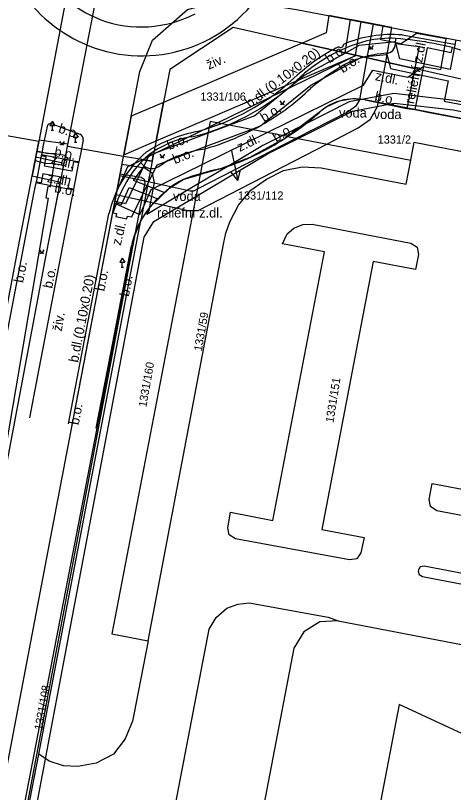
# Model space of a CAD drawing. Extents: x -601602 to -600882, y -1162594 to -1161950.
# Drawn here: x -601319.6 to -601273.9, y -1162415.3 to -1162334.3 of the extents above; entities that cross this region are included whole.
import ezdxf

# ---------------------------------------------------------------- set-up
doc = ezdxf.new("R2010")
doc.units = 0
for name, color, linetype in [('KN_Hranice parcel', 7, 'Continuous'), ('KN_Parcelní čísla', 7, 'Continuous'), ('KN_Pop  PČ popisy', 7, 'Continuous'), ('KN_Věcná břemena k části', 7, 'Continuous'), ('Vrstva 13', 7, 'Continuous'), ('Vrstva 16', 7, 'Continuous'), ('VRSTVA 3', 7, 'Continuous'), ('Vrstva 8', 7, 'Continuous')]:
    doc.layers.add(name, color=color, linetype=linetype)

# ---------------------------------------------------------------- blocks, each defined once
blk = doc.blocks.new('1029_20')
at = {"layer": 'KN_Pop  PČ popisy'}
for p, q in [((0, 0), (0.624, -2.935)), ((0.624, -2.935), (-0.074, -2.06)), ((0.624, -2.935), (0.906, -1.852))]:
    blk.add_line(p, q, dxfattribs=at)

msp = doc.modelspace()

# ---------------------------------------------------------------- linework, layer by layer
at = {"layer": 'KN_Hranice parcel'}
for p, q in [((-601314.03, -1162331.01), (-601317.17, -1162347.42)), ((-601314.18, -1162347.94), (-601311.29, -1162333.02)), ((-601317.17, -1162347.42), (-601323.06, -1162346.39)), ((-601291.23, -1162346.89), (-601278.38, -1162349.37)), ((-601308.33, -1162348.97), (-601314.18, -1162347.94)), ((-601305.34, -1162349.49), (-601308.33, -1162348.97)), ((-601305.34, -1162349.49), (-601306.52, -1162355.67)), ((-601317.16, -1162411.33), (-601306.52, -1162355.67)), ((-601318.63, -1162419.05), (-601317.16, -1162411.33))]:
    msp.add_line(p, q, dxfattribs=at)
for points in [[(-601308.33, -1162348.97), (-601306.64, -1162340.12), (-601305.31, -1162336.84), (-601301.64, -1162333.66), (-601297.4, -1162332.52), (-601290.3, -1162333.64), (-601266.25, -1162338.24), (-601260.29, -1162339.36), (-601231.3, -1162344.87), (-601139.53, -1162362.21), (-601062.38, -1162376.91), (-600987.54, -1162391.11), (-600950.39, -1162398.12), (-600929.75, -1162402.03), (-600920.358, -1162403.852)], [(-601139.85, -1162370.35), (-601175.08, -1162363.05), (-601223.43, -1162352.19), (-601296.88, -1162335.54), (-601303.51, -1162339.9), (-601305.34, -1162349.49)], [(-601139.85, -1162370.35), (-601160.69, -1162366.38), (-601240.23, -1162351.14), (-601240.29, -1162351.38), (-601283.17, -1162343.09), (-601284.42, -1162342.98), (-601285.85, -1162343.22), (-601287.2, -1162343.85), (-601291.23, -1162346.89)], [(-601291.23, -1162346.89), (-601299.28, -1162345.34), (-601300.34, -1162350.88)], [(-601291.23, -1162346.89), (-601291.42, -1162347.04), (-601295.15, -1162349.09), (-601298.21, -1162350.27), (-601300.34, -1162350.88)], [(-601342.45, -1162480.03), (-601331.27, -1162421.43), (-601325.33, -1162390.2), (-601319.3, -1162358.55), (-601317.17, -1162347.42)], [(-601341.27, -1162489.73), (-601339.53, -1162480.59), (-601328.28, -1162421.68), (-601322.37, -1162390.85), (-601316.38, -1162359.28), (-601314.18, -1162347.94)], [(-601278.38, -1162349.37), (-601278.02, -1162347.49), (-601254.54, -1162352.03), (-601255.6, -1162357.43), (-601255.57, -1162357.92), (-601255.42, -1162358.37), (-601255.14, -1162358.81), (-601254.79, -1162359.14), (-601254.3, -1162359.39), (-601253.78, -1162359.52), (-601248.91, -1162360.41), (-601255.63, -1162395.83), (-601276.99, -1162391.71), (-601277.39, -1162391.81), (-601277.58, -1162392.1), (-601277.61, -1162392.26), (-601277.52, -1162392.61), (-601277.17, -1162392.82), (-601255.44, -1162396.98)], [(-601331.86, -1162472.11), (-601325.48, -1162438.88), (-601316.05, -1162389.38), (-601308.33, -1162348.97)], [(-601305.77, -1162399.5), (-601297.86, -1162357.97), (-601297.67, -1162356.99), (-601297.26, -1162355.81), (-601296.33, -1162354.05), (-601295.05, -1162352.51), (-601293.43, -1162351.34), (-601291.64, -1162350.46), (-601289.7, -1162350.08), (-601287.72, -1162350.18), (-601278.86, -1162351.88), (-601278.38, -1162349.37)], [(-601300.34, -1162350.88), (-601309.53, -1162398.78), (-601305.77, -1162399.5)], [(-601306.52, -1162355.67), (-601305.51, -1162354.19), (-601303.5, -1162352.26), (-601302.11, -1162351.38), (-601300.34, -1162350.88)], [(-601234.25, -1162354.54), (-601234.7, -1162355.78), (-601234.11, -1162356.97), (-601234.63, -1162359.74), (-601243.89, -1162408.17), (-601267.03, -1162403.71), (-601268.2, -1162403.5), (-601269.36, -1162403.53), (-601270.46, -1162404), (-601271.29, -1162404.85), (-601271.72, -1162405.96), (-601271.71, -1162407.14), (-601271.24, -1162408.21), (-601270.39, -1162409.04), (-601269.24, -1162409.5), (-601268.45, -1162409.65), (-601268.79, -1162411.17), (-601279.61, -1162406.15), (-601285.53, -1162437.17)], [(-601306.52, -1162355.67), (-601307.3, -1162357.51), (-601317.48, -1162410.31), (-601328.81, -1162468.87), (-601328.82, -1162471.63), (-601328.74, -1162471.98)], [(-601284.77, -1162391.08), (-601296.65, -1162388.87), (-601297.3, -1162388.46), (-601297.46, -1162387.72), (-601297.16, -1162386.1), (-601292.76, -1162386.95), (-601287.37, -1162358.94), (-601291.77, -1162358.11), (-601291.26, -1162357.07), (-601290.56, -1162356.45), (-601289.65, -1162356.07), (-601288.66, -1162356.05), (-601278.36, -1162358.03), (-601277.72, -1162358.45), (-601277.59, -1162359.21), (-601277.88, -1162360.77), (-601282.29, -1162359.93), (-601287.64, -1162387.9), (-601283.24, -1162388.75), (-601283.59, -1162390.34), (-601284, -1162390.97), (-601284.77, -1162391.08)], [(-601271.75, -1162383.95), (-601267.66, -1162362.74), (-601272.09, -1162361.89), (-601271.78, -1162360.33), (-601271.37, -1162359.69), (-601270.63, -1162359.51), (-601261.34, -1162361.33), (-601260.68, -1162361.76), (-601260.53, -1162362.5), (-601260.81, -1162364.07), (-601265.22, -1162363.22), (-601269.27, -1162384.43), (-601264.86, -1162385.28), (-601265.18, -1162386.93), (-601265.59, -1162387.56), (-601266.34, -1162387.73), (-601275.68, -1162385.94), (-601276.32, -1162385.51), (-601276.46, -1162384.76), (-601276.15, -1162383.11), (-601271.75, -1162383.95)], [(-601301.62, -1162482.78), (-601280.33, -1162486.8), (-601279.35, -1162481.79), (-601277.9, -1162482.08), (-601277.64, -1162482.08), (-601277.55, -1162481.88), (-601277.52, -1162481.7), (-601272.48, -1162482.63), (-601265.97, -1162448.61), (-601302.27, -1162441.78), (-601304.31, -1162441.04), (-601306.1, -1162439.45), (-601306.76, -1162438.09), (-601306.72, -1162436.52), (-601299.4, -1162398.31), (-601298.68, -1162397.07), (-601297.55, -1162396.12), (-601296.41, -1162395.68), (-601295.22, -1162395.55), (-601286.98, -1162397.06), (-601285.95, -1162397.42)], [(-601285.95, -1162397.42), (-601287.86, -1162397.52), (-601289.54, -1162398.56), (-601290.58, -1162400.27), (-601297.91, -1162438.61), (-601297.76, -1162440.13), (-601297.11, -1162441.39), (-601296.13, -1162442.29), (-601294.57, -1162442.91), (-601265.31, -1162448.49), (-601274.56, -1162496.89), (-601274.6, -1162498.05), (-601274.28, -1162499.02), (-601273.37, -1162500.08), (-601272.15, -1162500.6), (-601303.87, -1162494.56)], [(-601285.95, -1162397.42), (-601256.61, -1162403.05), (-601255.44, -1162396.98)], [(-601305.77, -1162399.5), (-601307.27, -1162407.39), (-601307.38, -1162407.88), (-601308.15, -1162409.74), (-601309.38, -1162411.32), (-601311.16, -1162412.28), (-601313.09, -1162412.62), (-601314.58, -1162412.56), (-601316.09, -1162412.07), (-601317.16, -1162411.33)]]:
    msp.add_lwpolyline(points, dxfattribs=at)
at = {"layer": 'KN_Pop  PČ popisy'}
msp.add_line((-601297.08, -1162348.34), (-601297.03, -1162348.57), dxfattribs=at)
at = {"layer": 'KN_Věcná břemena k části'}
for points in [[(-601284.16, -1162338.42), (-601283.57, -1162334.93), (-601286.91, -1162334.29), (-601287.21, -1162336.1), (-601289.71, -1162337.17)], [(-601281, -1162339.14), (-601280.35, -1162335.54), (-601282.31, -1162335.17), (-601282.95, -1162338.7), (-601283.74, -1162343.07), (-601284.11, -1162343.72), (-601284.92, -1162344.31), (-601290.29, -1162347.08), (-601300.64, -1162352.41), (-601301.03, -1162352.61), (-601301.37, -1162352.61), (-601305.75, -1162351.64), (-601308.72, -1162350.99), (-601309.09, -1162352.95), (-601306.13, -1162353.61), (-601301.59, -1162354.61), (-601301.06, -1162354.61), (-601300.55, -1162354.61), (-601287.13, -1162347.69), (-601283.88, -1162346.01), (-601282.59, -1162345.08), (-601281.84, -1162343.77)], [(-601277.06, -1162339.6), (-601275.24, -1162339.92), (-601274.68, -1162336.7), (-601277.8, -1162336.16), (-601279.4, -1162337.25), (-601281.5, -1162336.82), (-601281.26, -1162335.37), (-601284.7, -1162334.71), (-601285.27, -1162338.17), (-601284.16, -1162338.42), (-601277.54, -1162339.92)], [(-601284.17, -1162338.5), (-601284.16, -1162338.42), (-601289.71, -1162337.17), (-601304.17, -1162343.34), (-601304.93, -1162347.36)], [(-601299.39, -1162345.93), (-601305.2, -1162348.76), (-601305.34, -1162349.49), (-601306.34, -1162349.32), (-601307.9, -1162350.08), (-601309.03, -1162352.62), (-601309.27, -1162353.87), (-601306.61, -1162355.05), (-601306.25, -1162354.24), (-601305.44, -1162352.44), (-601300.14, -1162349.83), (-601293.35, -1162346.48), (-601283.3, -1162341.53), (-601282.34, -1162339.97), (-601278.7, -1162340.71), (-601277.54, -1162339.92), (-601284.16, -1162338.42), (-601284.17, -1162338.5), (-601285.43, -1162339.11), (-601298.5, -1162345.49)], [(-601307.53, -1162344.77), (-601308.3, -1162348.8), (-601304.93, -1162347.36), (-601304.17, -1162343.34)], [(-601314.56, -1162349.88), (-601314.37, -1162348.9), (-601315.51, -1162348.72), (-601316.36, -1162348.68), (-601317.36, -1162348.44), (-601317.55, -1162349.42), (-601316.5, -1162349.68), (-601315.61, -1162349.72)], [(-601306.34, -1162349.32), (-601305.34, -1162349.49), (-601305.2, -1162348.76)], [(-601314.9, -1162351.66), (-601314.52, -1162349.7), (-601317.48, -1162349.05), (-601317.86, -1162351.01)]]:
    msp.add_lwpolyline(points, close=True, dxfattribs=at)
for points in [[(-601273.67, -1162336.82), (-601274.26, -1162339.91), (-601279.51, -1162338.79), (-601279.97, -1162337.03), (-601283.8, -1162337.42), (-601285.2, -1162338.19), (-601289.49, -1162340.55), (-601294.65, -1162344.73), (-601297.29, -1162345.72), (-601299.51, -1162346.56), (-601305.19, -1162348.71), (-601305.68, -1162348.89), (-601305.92, -1162349.39), (-601308.13, -1162353.91), (-601308.22, -1162353.89), (-601309.23, -1162353.67), (-601309.45, -1162354.86), (-601309.06, -1162354.94), (-601309.13, -1162355.24), (-601307.97, -1162355.5), (-601307.9, -1162355.2), (-601307.47, -1162355.29), (-601305.79, -1162351.84), (-601304.82, -1162349.85), (-601299.78, -1162347.95), (-601295.03, -1162346.16), (-601294.05, -1162345.79), (-601288.81, -1162341.55), (-601283.45, -1162338.58), (-601280.87, -1162338.33), (-601280.64, -1162339.22), (-601280.49, -1162339.81), (-601274.48, -1162341.09), (-601274.89, -1162343.21), (-601244.97, -1162348.96)], [(-601218.98, -1162353.53), (-601238.41, -1162350.37), (-601243.06, -1162349.26), (-601273.81, -1162343.13), (-601280.15, -1162342.41), (-601284.8, -1162343.3), (-601291.73, -1162346.8), (-601293.8, -1162347.85), (-601297.27, -1162349.91), (-601300.53, -1162351.84), (-601305.9, -1162355.03), (-601305.64, -1162354.61), (-601305.08, -1162351.7), (-601305.31, -1162350.75), (-601305.55, -1162350.59), (-601306.12, -1162350.2), (-601308.49, -1162349.83), (-601308.68, -1162350.81), (-601306.5, -1162351.16), (-601306.19, -1162351.36), (-601306.11, -1162351.72), (-601307.13, -1162357.13), (-601328.23, -1162468.65)], [(-601326.07, -1162462.59), (-601306.17, -1162357.4), (-601305.17, -1162355.77), (-601300.78, -1162353.16), (-601293.32, -1162348.72), (-601290.12, -1162347.11), (-601284.47, -1162344.26), (-601280.11, -1162343.42), (-601273.96, -1162344.12), (-601243.27, -1162350.24), (-601238.6, -1162351.35), (-601219.15, -1162354.51), (-601164.77, -1162365.18), (-601141.49, -1162369.75)], [(-601322.37, -1162390.85), (-601316.38, -1162359.28), (-601315.17, -1162353.02), (-601314.18, -1162347.94), (-601314.13, -1162347.7), (-601317.15, -1162347.29), (-601317.17, -1162347.42), (-601317.37, -1162348.47), (-601315.42, -1162348.73), (-601315.97, -1162352.15), (-601316.22, -1162352.11), (-601316.42, -1162353.31), (-601316.17, -1162353.35), (-601322.79, -1162391.91)]]:
    msp.add_lwpolyline(points, dxfattribs=at)
at = {"layer": 'Vrstva 13'}
for p, q in [((-601279.98, -1162337.2), (-601279.95, -1162336.66)), ((-601279.28, -1162336.31), (-601273.82, -1162337.26)), ((-601279.98, -1162337.2), (-601277.51, -1162337.5)), ((-601277.51, -1162337.5), (-601278.79, -1162343.98)), ((-601276.69, -1162337.64), (-601277.95, -1162344.1)), ((-601274.16, -1162338.16), (-601276.69, -1162337.64)), ((-601274.05, -1162337.61), (-601275.98, -1162337.21)), ((-601274.16, -1162338.16), (-601274.05, -1162337.61)), ((-601274.05, -1162337.61), (-601273.07, -1162337.91)), ((-601291.5, -1162341.65), (-601290.21, -1162340.51)), ((-601292.23, -1162342.72), (-601290.69, -1162341.47)), ((-601283.15, -1162343.09), (-601278.79, -1162343.98)), ((-601278.79, -1162343.98), (-601277.95, -1162344.1)), ((-601277.95, -1162344.1), (-601276.26, -1162344.42)), ((-601276.26, -1162344.42), (-601262.05, -1162347.19)), ((-601315.68, -1162345.6), (-601312.88, -1162346.66)), ((-601316.3, -1162345.85), (-601316.7, -1162347.82)), ((-601312.54, -1162347.25), (-601312.78, -1162348.57)), ((-601301.21, -1162346.92), (-601300.24, -1162346.7)), ((-601316.7, -1162347.82), (-601316.89, -1162348.8)), ((-601316.92, -1162348.92), (-601317.44, -1162351.66)), ((-601316.89, -1162348.8), (-601316.92, -1162348.92)), ((-601316.38, -1162349.02), (-601316.92, -1162348.92)), ((-601313.52, -1162349.46), (-601316.89, -1162348.8)), ((-601316.56, -1162349.99), (-601316.38, -1162349.02)), ((-601312.78, -1162348.57), (-601312.99, -1162349.56)), ((-601313.537, -1162349.547), (-601313.73, -1162350.5)), ((-601313.01, -1162349.65), (-601313.54, -1162352.38)), ((-601313.01, -1162349.65), (-601313.537, -1162349.547)), ((-601312.99, -1162349.56), (-601313.52, -1162349.46)), ((-601312.99, -1162349.56), (-601313.01, -1162349.65)), ((-601306.54, -1162349.62), (-601306.16, -1162349.99)), ((-601304.66, -1162350.02), (-601303.84, -1162349.49)), ((-601313.73, -1162350.5), (-601316.56, -1162349.99)), ((-601307.3, -1162351.48), (-601306.16, -1162349.99)), ((-601316.72, -1162350.81), (-601316.92, -1162351.75)), ((-601313.88, -1162351.33), (-601316.72, -1162350.81)), ((-601314.08, -1162352.3), (-601313.88, -1162351.33)), ((-601317.47, -1162351.75), (-601317.67, -1162352.72)), ((-601317.44, -1162351.66), (-601317.47, -1162351.75)), ((-601313.55, -1162352.5), (-601317.47, -1162351.75)), ((-601316.92, -1162351.75), (-601317.44, -1162351.66)), ((-601308.54, -1162354), (-601307.73, -1162352.21)), ((-601307.73, -1162352.21), (-601304.76, -1162353.39)), ((-601304.1, -1162352.74), (-601307.3, -1162351.48)), ((-601317.67, -1162352.72), (-601321.02, -1162370.16)), ((-601313.54, -1162352.38), (-601314.08, -1162352.3)), ((-601313.55, -1162352.5), (-601313.75, -1162353.48)), ((-601313.54, -1162352.38), (-601313.55, -1162352.5)), ((-601313.75, -1162353.48), (-601317.14, -1162371.15)), ((-601309.06, -1162353.81), (-601308.54, -1162354)), ((-601312.56, -1162369.06), (-601309.85, -1162354.98)), ((-601312.18, -1162369.17), (-601309.43, -1162354.88)), ((-601309.66, -1162369.51), (-601307.5, -1162358.29)), ((-601314.058, -1162376.885), (-601312.56, -1162369.06)), ((-601311.163, -1162377.34), (-601309.66, -1162369.51)), ((-601317.14, -1162371.15), (-601318.122, -1162376.247))]:
    msp.add_line(p, q, dxfattribs=at)
for centre, radius, start, end in [((-601306.343, -1162323.316), 12.204, 205.81196, 249.13589), ((-601306.785, -1162323.065), 15.548, 295.99581, 337.60006), ((-601306.156, -1162323.027), 15.52, 219.21986, 255.31685), ((-601306.471, -1162323.199), 12.27, 249.88788, 297.21399), ((-601280.409, -1162348.859), 12.599, 84.85864, 113.33652), ((-601280.45, -1162348.092), 11.443, 87.49566, 102.72211), ((-601284.05, -1162380.857), 44.386, 79.52483, 84.70017), ((-601306.439, -1162323.284), 15.201, 256.10125, 295.18539), ((-601278.82, -1162352.821), 16.424, 104.63667, 136.28144), ((-601277.719, -1162354.024), 18.403, 116.39461, 132.74647), ((-601285.701, -1162337.314), 0.302, 228.64815, 4.48195), ((-601280.976, -1162337.224), 0.996, 270.92224, 1.36928), ((-601280.169, -1162349.88), 11.686, 93.88244, 112.33598), ((-601274.677, -1162358.551), 21.867, 117.01481, 130.36533), ((-601307.172, -1162322.548), 24.709, 285.30558, 309.36691), ((-601306.205, -1162323.961), 24.96, 300.30579, 314.08465), ((-601307.333, -1162322.375), 25.338, 286.25568, 306.58795), ((-601284.254, -1162348.385), 5.409, 78.21763, 132.23123), ((-601308.291, -1162320.993), 31.035, 309.23936, 311.0998), ((-601315.885, -1162345.985), 0.437, 61.98823, 161.9329), ((-601306.85, -1162323.262), 25.889, 285.25123, 300.75823), ((-601308.045, -1162321.338), 30.612, 301.85234, 309.29011), ((-601297.781, -1162361.04), 14.938, 101.07334, 123.19764), ((-601313.03, -1162347.14), 0.503, 347.32186, 72.58536), ((-601299.567, -1162356.999), 10.212, 99.26076, 127.61764), ((-601306.475, -1162324.165), 27.383, 287.50277, 302.18476), ((-601298.12, -1162357.67), 12.034, 130.65083, 167.08209), ((-601299.053, -1162356.682), 10.292, 130.95896, 147.87949), ((-601298.052, -1162360.684), 12.602, 99.07605, 117.34092), ((-601305.389, -1162348.965), 1.283, 233.06232, 304.64616), ((-601294.019, -1162372.487), 22.605, 100.76154, 110.97276), ((-601294.302, -1162359.512), 15.821, 148.34861, 162.97538), ((-601297.857, -1162359.739), 9.379, 116.96671, 137.39324), ((-601298.094, -1162360.334), 9.625, 133.8315, 167.74209), ((-626109.111, -1157627.22), 25246.265, 349.155988, 349.1739556)]:
    msp.add_arc(centre, radius, start, end, dxfattribs=at)
at = {"layer": 'VRSTVA 3'}
for points in [[(-601282.772, -1162337.41), (-601282.522, -1162337.785), (-601282.272, -1162337.41)], [(-601292.023, -1162343.187), (-601291.773, -1162343.562), (-601291.523, -1162343.187)], [(-601314.986, -1162347.405), (-601314.736, -1162347.78), (-601314.486, -1162347.405)], [(-601304.536, -1162348.75), (-601304.286, -1162349.125), (-601304.036, -1162348.75)], [(-601317.093, -1162358.726), (-601316.843, -1162359.101), (-601316.593, -1162358.726)]]:
    msp.add_lwpolyline(points, dxfattribs=at)
for centre in [(-601282.647, -1162337.76), (-601282.397, -1162337.76), (-601291.898, -1162343.537), (-601291.648, -1162343.537), (-601314.861, -1162347.755), (-601314.611, -1162347.755), (-601304.411, -1162349.1), (-601304.161, -1162349.1), (-601316.968, -1162359.076), (-601316.718, -1162359.076)]:
    msp.add_circle(centre, 0.025, dxfattribs=at)
at = {"layer": 'Vrstva 8'}
for p, q in [((-601315.74, -1162345.307), (-601315.99, -1162345.74)), ((-601315.99, -1162345.74), (-601315.49, -1162345.74)), ((-601315.74, -1162345.307), (-601315.49, -1162345.74)), ((-601315.74, -1162346.24), (-601315.74, -1162345.74)), ((-601315.865, -1162346.24), (-601315.615, -1162346.24)), ((-601313.32, -1162346.547), (-601313.57, -1162346.98)), ((-601313.32, -1162346.547), (-601313.07, -1162346.98)), ((-601313.57, -1162346.98), (-601313.07, -1162346.98)), ((-601313.32, -1162347.48), (-601313.32, -1162346.98)), ((-601313.445, -1162347.48), (-601313.195, -1162347.48)), ((-601308.45, -1162359.587), (-601308.7, -1162360.02)), ((-601308.7, -1162360.02), (-601308.2, -1162360.02)), ((-601308.45, -1162359.587), (-601308.2, -1162360.02)), ((-601308.45, -1162360.52), (-601308.45, -1162360.02)), ((-601308.575, -1162360.52), (-601308.325, -1162360.52))]:
    msp.add_line(p, q, dxfattribs=at)

# ---------------------------------------------------------------- block references
at = {"layer": 'KN_Pop  PČ popisy'}
msp.add_blockref('1029_20', (-601297.03, -1162348.57), dxfattribs=at)

# ---------------------------------------------------------------- texts
at = {"layer": 'KN_Parcelní čísla'}
for s, p in [('1331/106', (-601300.31, -1162343.16)), ('1331/2', (-601281.83, -1162347.64)), ('1331/112', (-601296.4, -1162353.483))]:
    msp.add_text(s, height=0.85, dxfattribs=at).set_placement(p)
for s, rotation, p in [('1331/59', 80, (-601300.172, -1162369.347)), ('1331/160', 80, (-601305.948, -1162375.184)), ('1331/151', 81, (-601286.444, -1162376.801)), ('1331/108', 80, (-601316.792, -1162408.887))]:
    msp.add_text(s, height=0.85, rotation=rotation, dxfattribs=at).set_placement(p)
at = {"layer": 'Vrstva 16'}
for s, rotation, p in [('reliéfní z.dl.', 78.96323, (-601278.053, -1162343.553)), ('b.dl.(0.10x0.20)', 37.1811, (-601295.137, -1162343.955)), ('b.o.', 35.16631, (-601286.852, -1162339.308)), ('živ.', 23.06825, (-601299.435, -1162339.937)), ('b.o.', 33.247, (-601285.468, -1162340.319)), ('z.dl.', 348.13773, (-601282.152, -1162341.01)), ('b.o.', 347.82227, (-601282.209, -1162343.148)), ('b.o.', 31.80036, (-601293.683, -1162345.435)), ('b.o.', 341.39963, (-601315.193, -1162346.456)), ('b.o.', 31.80036, (-601292.411, -1162347.516)), ('b.o.', 21.65191, (-601303.562, -1162348.328)), ('z.dl.', 25.61061, (-601296.215, -1162348.511)), ('b.o.', 349.25281, (-601315.602, -1162348.929)), ('z.dl.', 348.23885, (-601315.976, -1162349.749)), ('b.o.', 21.65191, (-601302.967, -1162349.789)), ('z.dl.', 349.27657, (-601316.347, -1162351.645)), ('b.o.', 349.25281, (-601315.584, -1162352.717)), ('z.dl.', 76.38237, (-601308.624, -1162358.328)), ('b.o.', 78.68713, (-601318.799, -1162362.218)), ('b.o.', 78.68713, (-601315.766, -1162362.807)), ('b.o.', 79.11143, (-601310.322, -1162363.092)), ('b.dl.(0.10x0.20)', 79.16532, (-601313.066, -1162370.531)), ('b.o.', 79.11143, (-601307.775, -1162363.653)), ('živ.', 80.08118, (-601314.777, -1162367.274)), ('b.o.', 79.13355, (-601313, -1162377.046))]:
    msp.add_text(s, height=1, rotation=rotation, dxfattribs=at).set_placement(p)
for s, p in [('voda', (-601285.864, -1162344.919)), ('voda', (-601282.249, -1162345.079)), ('voda', (-601303.171, -1162353.629)), ('reliéfní z.dl.', (-601304.828, -1162355.355))]:
    msp.add_text(s, height=1, dxfattribs=at).set_placement(p)

doc.saveas('drawing.dxf')
